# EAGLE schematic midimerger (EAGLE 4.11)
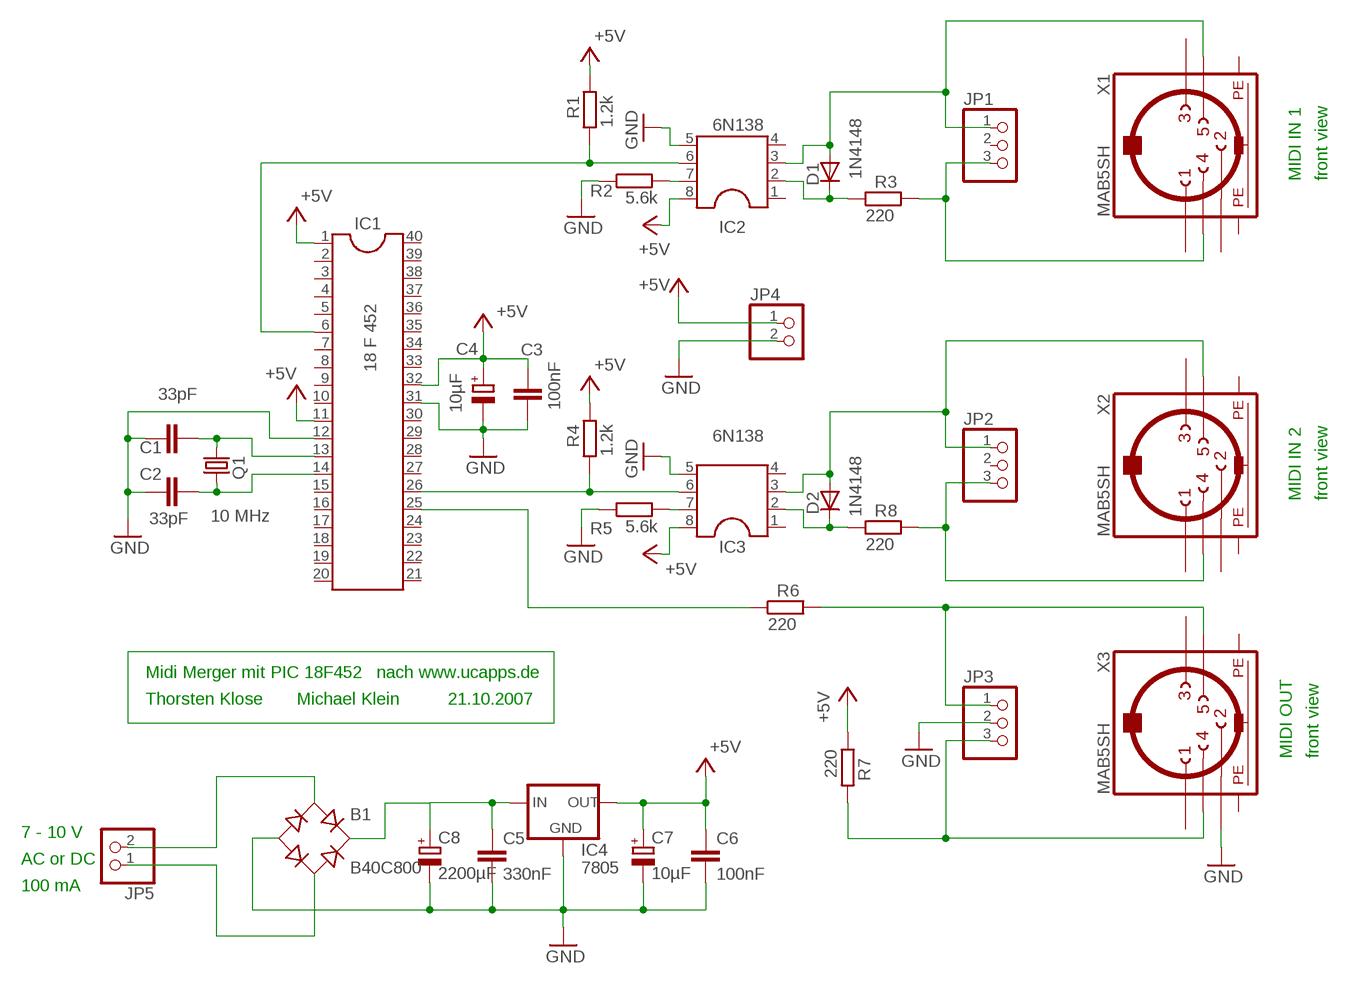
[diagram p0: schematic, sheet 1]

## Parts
B1  B40C800  RB1A  [RB1A]
C1  33pF  C-EU025-024X044  [C025-024X044]
C2  33pF  C-EU025-024X044  [C025-024X044]
C3  100nF  C-EU025-024X044  [C025-024X044]
C4  10µF  CPOL-EUE2,5-6E  [E2,5-6E]
C5  330nF  C-EU050-025X075  [C050-025X075]
C6  100nF  C-EU025-024X044  [C025-024X044]
C7  10µF  CPOL-EUE2,5-6E  [E2,5-6E]
C8  2200µF  CPOL-EUE5-13  [E5-13]
D1  1N4148  [DO35-10]
D2  1N4148  [DO35-10]
IC1  18 F 452  DIL40  [DIL40]
IC2  6N138  DIL8  [DIL08]
IC3  6N138  DIL8  [DIL08]
IC4  7805  78XXS  [78XXS]
JP1  PINHD-1X3  [1X03]
JP2  PINHD-1X3  [1X03]
JP3  PINHD-1X3  [1X03]
JP4  PINHD-1X2  [1X02]
JP5  PINHD-1X2  [1X02]
Q1  10 MHz  CRYTALHC18U-V  [HC18U-V]
R1  1.2k  R-EU_0207/10  [0207/10]
R2  5.6k  R-EU_0207/10  [0207/10]
R3  220  R-EU_0207/10  [0207/10]
R4  1.2k  R-EU_0207/10  [0207/10]
R5  5.6k  R-EU_0207/10  [0207/10]
R6  220  R-EU_0207/10  [0207/10]
R7  220  R-EU_0207/10  [0207/10]
R8  220  R-EU_0207/10  [0207/10]
X1  MAB5SH  [MAB5SH]
X2  MAB5SH  [MAB5SH]
X3  MAB5SH  [MAB5SH]

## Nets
+5V: C3.1 C4.+ C6.1 C7.+ IC1.1 IC1.11 IC1.32 IC2.8 IC3.8 IC4.OUT JP4.1 R1.2 R4.2 R7.1
GND: B1.- C1.1 C2.1 C3.2 C4.- C5.2 C6.2 C7.- C8.- IC1.12 IC1.31 IC2.5 IC3.5 IC4.GND JP3.2 JP4.2 R2.1 R5.1 X3.2
N$1: C1.2 IC1.13 Q1.2
N$2: C2.2 IC1.14 Q1.1
N$3: IC1.26 IC3.6 R4.1
N$4: IC3.7 R5.2
N$5: D2.C IC3.2 R8.1
N$6: JP2.3 R8.2 X2.4
N$7: IC1.6 IC2.6 R1.1
N$8: IC2.7 R2.2
N$9: D1.A IC2.3 JP1.1 X1.5
N$10: D1.C IC2.2 R3.1
N$11: JP1.3 R3.2 X1.4
N$12: D2.A IC3.3 JP2.1 X2.5
N$15: JP3.1 R6.2 X3.5
N$16: JP3.3 R7.2 X3.4
N$18: IC1.25 R6.1
N$22: B1.+ C5.1 C8.+ IC4.IN
N$24: B1.AC1 JP5.2
N$25: B1.AC2 JP5.1
Unconnected: IC1.2 IC1.3 IC1.4 IC1.5 IC1.7 IC1.8 IC1.9 IC1.10 IC1.15 IC1.16 IC1.17 IC1.18 IC1.19 IC1.20 IC1.21 IC1.22 IC1.23 IC1.24 IC1.27 IC1.28 IC1.29 IC1.30 IC1.33 IC1.34 IC1.35 IC1.36 IC1.37 IC1.38 IC1.39 IC1.40 IC2.1 IC2.4 IC3.1 IC3.4 JP1.2 JP2.2 X1.1 X1.2 X1.3 X2.1 X2.2 X2.3 X3.1 X3.3

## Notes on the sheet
- MIDI IN 1 | front view
- MIDI IN 2 | front view
- Midi Merger mit PIC 18F452 | nach www.ucapps.de
- Thorsten Klose | Michael Klein | 21.10.2007
- MIDI OUT | front view
- 7 - 10 V
- AC or DC
- 100 mA

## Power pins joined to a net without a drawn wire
PE: X1.PE X1.PE@(PE) X2.PE X2.PE@(PE) X3.PE X3.PE@(PE)

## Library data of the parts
B1 = rectifier:RB1A: RECTIFIER 1 A
C1-C3 C5 C6 = rcl:C-EU: CAPACITOR, European symbol
C4 C7 C8 = rcl:CPOL-EU: POLARIZED CAPACITOR, European symbol
D1 D2 = diode:1N4148: DIODE
IC1 = ic-package:DIL40: Dual In Line
IC2 IC3 = ic-package:DIL8: Dual In Line
IC4 = v-reg:78XXS: VOLTAGE REGULATOR
JP1-JP3 = pinhead:PINHD-1X3: PIN HEADER
JP4 JP5 = pinhead:PINHD-1X2: PIN HEADER
Q1 = crystal:CRYTAL: CRYSTAL
R1-R8 = rcl:R-EU_: RESISTOR, European symbol
X1-X3 = con-hirschmann:MAB5SH: Female CONNECTOR 5 pins 90 deg. with shield, horizontal (DIN 41524)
